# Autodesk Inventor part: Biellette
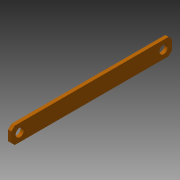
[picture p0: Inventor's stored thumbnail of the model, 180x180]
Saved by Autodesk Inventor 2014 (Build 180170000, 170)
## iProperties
Created: 2015-09
Part Number: Biellette
Material: Générique
Document SubType Name: Modeling
Designer: OL
Density: 1 g/cm^3
Appearance: Par défaut
Author: OL
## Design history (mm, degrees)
sketch "Esquisse1"
  geometry: L1 (-25, 25)-(455, 25); L2 (455, 25)-(455, -25); L3 (455, -25)-(-25, -25); L4 (-25, -25)-(-25, 25); C1 r 12.5 at (0, 0); C2 r 12.5 at (430, 0); 1 further point
  constraints: 8 end point, 2 centre point, 2 parallel, 1 coincident, 1 horizontal, 1 perpendicular
  dimensions: "d2" = 50 distance of L3.end L1.start; "d3" = 25 distance from line of L1 point (0, 0); "d4" = 25 distance from line of L4 point (0, 0); "d5" = 25 diameter of C1; "d6" = 25 diameter of C2; "d7" = 25 distance from line of L2 C2.centre; "d8" = 25 distance from line of L1 C2.centre; "d14" = 430 distance of C2.centre point (0, 0)
extrude "Extrusion1" new body sketch "Esquisse1" distance "d9" = 10; taper "d10" = 0 deg
chamfer "Chanfrein1" distance "d11" = 10; stored, may be unused: second distance "d12" = 2, angle "d13" = 45 deg
node "Solide1"
